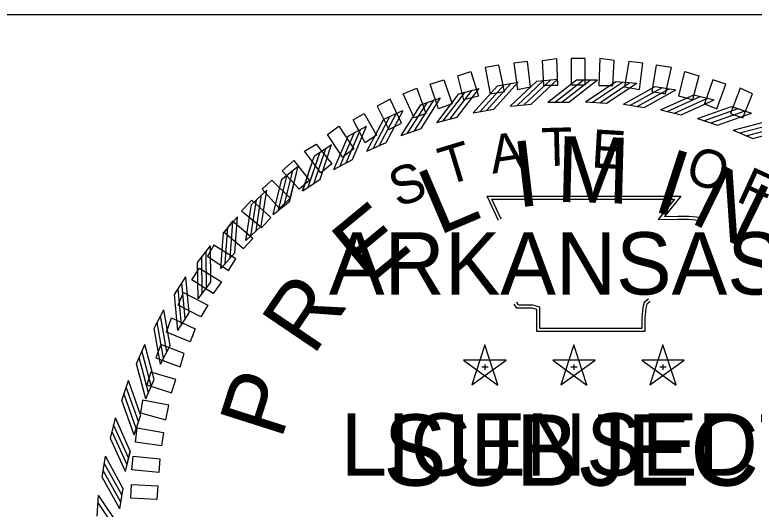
# Model space of a CAD drawing. Extents: x 16 to 1228740, y 11 to 152440.
# Drawn here: x 17.6649 to 17.7977, y 10.9098 to 10.9986 of the extents above; entities that cross this region are included whole.
import ezdxf

# ---------------------------------------------------------------- set-up
doc = ezdxf.new("R2010")
doc.units = 0
for name, color, linetype in [('R_No Plot', 7, 'Continuous'), ('STAMP_FRED', 7, 'Continuous'), ('STAMP_JUSTIN', 7, 'Continuous'), ('STAMP_PRELIM', 7, 'Continuous')]:
    doc.layers.add(name, color=color, linetype=linetype)

msp = doc.modelspace()

# ---------------------------------------------------------------- linework, layer by layer
at = {"layer": 'R_No Plot'}
msp.add_line((17.888, 10.99864), (17.47349, 10.99864), dxfattribs=at)
at = {"layer": 'STAMP_FRED'}
for p, q in [((17.75163, 10.98587), (17.75535, 10.98652)), ((17.75869, 10.98671), (17.76244, 10.98706)), ((17.76583, 10.98692), (17.7696, 10.98692)), ((17.77289, 10.98664), (17.77665, 10.98636)), ((17.74467, 10.98445), (17.74832, 10.9854)), ((17.77994, 10.98572), (17.78366, 10.98514)), ((17.78688, 10.98423), (17.79055, 10.98334)), ((17.73785, 10.98245), (17.7414, 10.98371)), ((17.75393, 10.98224), (17.7577, 10.98259)), ((17.76068, 10.98291), (17.76446, 10.98291)), ((17.76746, 10.98302), (17.77123, 10.98274)), ((17.77423, 10.98256), (17.77796, 10.98197)), ((17.73122, 10.9799), (17.73465, 10.98145)), ((17.74726, 10.98102), (17.75098, 10.98168)), ((17.78094, 10.98155), (17.78461, 10.98066)), ((17.79369, 10.98217), (17.79726, 10.98098)), ((17.74072, 10.97926), (17.74437, 10.98022)), ((17.78754, 10.97999), (17.79112, 10.97879)), ((17.72482, 10.97681), (17.72811, 10.97864)), ((17.73434, 10.97696), (17.7379, 10.97821)), ((17.79398, 10.97789), (17.79746, 10.9764)), ((17.71869, 10.97321), (17.72183, 10.9753)), ((17.72817, 10.97413), (17.73161, 10.97568)), ((17.72225, 10.97081), (17.72556, 10.97264)), ((17.71289, 10.96911), (17.71584, 10.97145)), ((17.71664, 10.96702), (17.71978, 10.96911)), ((17.70744, 10.96454), (17.71019, 10.96712)), ((17.71135, 10.96277), (17.71431, 10.96512)), ((17.70239, 10.95954), (17.70492, 10.96234)), ((17.70643, 10.9581), (17.70919, 10.96068)), ((17.69777, 10.95414), (17.70006, 10.95714)), ((17.70192, 10.95304), (17.70445, 10.95584)), ((17.69361, 10.94838), (17.69564, 10.95156)), ((17.69784, 10.94762), (17.70013, 10.95062)), ((17.68994, 10.9423), (17.69171, 10.94563)), ((17.69422, 10.94189), (17.69625, 10.94507)), ((17.68679, 10.93593), (17.68827, 10.93939)), ((17.69108, 10.93587), (17.69285, 10.93921)), ((17.74935, 10.93936), (17.747, 10.93212)), ((17.7517, 10.93212), (17.74936, 10.93936)), ((17.76534, 10.93936), (17.76299, 10.93212)), ((17.76769, 10.93212), (17.76535, 10.93936)), ((17.78134, 10.93936), (17.77898, 10.93212)), ((17.78369, 10.93212), (17.78134, 10.93936)), ((17.75316, 10.93659), (17.74555, 10.9366)), ((17.74555, 10.93659), (17.7517, 10.93211)), ((17.747, 10.93212), (17.75317, 10.93659)), ((17.76915, 10.93659), (17.76154, 10.9366)), ((17.76154, 10.93659), (17.7677, 10.93211)), ((17.763, 10.93212), (17.76916, 10.93659)), ((17.78514, 10.93659), (17.77753, 10.9366)), ((17.77753, 10.93659), (17.78369, 10.93211)), ((17.77899, 10.93212), (17.78515, 10.93659)), ((17.74881, 10.93538), (17.74994, 10.93538)), ((17.74936, 10.93578), (17.74936, 10.93483)), ((17.7648, 10.93538), (17.76593, 10.93538)), ((17.76535, 10.93578), (17.76535, 10.93483)), ((17.78079, 10.93538), (17.78193, 10.93538)), ((17.78134, 10.93578), (17.78134, 10.93483)), ((17.68417, 10.92932), (17.68536, 10.9329)), ((17.68845, 10.92962), (17.68994, 10.93309)), ((17.68635, 10.92317), (17.68755, 10.92676)), ((17.68211, 10.92252), (17.683, 10.92618)), ((17.68479, 10.91657), (17.68568, 10.92024)), ((17.68061, 10.91557), (17.6812, 10.9193)), ((17.68378, 10.90987), (17.68437, 10.9136)), ((17.6797, 10.90852), (17.67998, 10.91228))]:
    msp.add_line(p, q, dxfattribs=at)
for points in [[(17.75098, 10.98168), (17.75535, 10.98653)], [(17.75393, 10.98224), (17.75868, 10.98671)], [(17.75514, 10.98234), (17.75989, 10.98681)], [(17.75644, 10.98249), (17.76119, 10.98696)], [(17.75769, 10.98259), (17.76245, 10.98706)], [(17.76068, 10.98291), (17.76582, 10.98692)], [(17.76189, 10.9829), (17.76704, 10.98691)], [(17.7632, 10.98292), (17.76835, 10.98694)], [(17.76446, 10.98291), (17.7696, 10.98692)], [(17.76746, 10.98301), (17.77288, 10.98664)], [(17.76867, 10.98291), (17.77409, 10.98654)], [(17.76998, 10.98284), (17.7754, 10.98647)], [(17.74436, 10.98022), (17.74832, 10.98541)], [(17.74726, 10.98102), (17.75163, 10.98586)], [(17.74846, 10.98122), (17.75282, 10.98606)], [(17.74974, 10.98148), (17.75411, 10.98632)], [(17.77123, 10.98274), (17.77665, 10.98636)], [(17.77423, 10.98256), (17.77993, 10.98572)], [(17.77542, 10.98236), (17.78113, 10.98552)], [(17.77672, 10.98218), (17.78243, 10.98535)], [(17.74071, 10.97925), (17.74467, 10.98444)], [(17.74189, 10.97955), (17.74584, 10.98474)], [(17.74315, 10.97991), (17.7471, 10.9851)], [(17.77796, 10.98198), (17.78366, 10.98514)], [(17.78093, 10.98155), (17.78688, 10.98423)], [(17.78211, 10.98125), (17.78805, 10.98393)], [(17.73548, 10.97734), (17.73899, 10.98284)], [(17.73671, 10.97781), (17.74022, 10.98331)], [(17.73789, 10.97822), (17.74141, 10.98371)], [(17.78339, 10.98097), (17.78933, 10.98365)], [(17.7846, 10.98066), (17.79055, 10.98334)], [(17.73161, 10.97568), (17.73466, 10.98145)], [(17.73433, 10.97695), (17.73784, 10.98245)], [(17.78753, 10.97999), (17.79368, 10.98217)], [(17.78868, 10.97959), (17.79483, 10.98177)], [(17.78993, 10.9792), (17.79608, 10.98139)], [(17.72817, 10.97413), (17.73121, 10.9799)], [(17.72928, 10.97462), (17.73232, 10.98038)], [(17.73046, 10.97518), (17.73351, 10.98095)], [(17.79112, 10.9788), (17.79727, 10.98098)], [(17.72556, 10.97264), (17.72812, 10.97864)], [(17.79398, 10.97788), (17.80029, 10.97955)], [(17.79509, 10.9774), (17.8014, 10.97906)], [(17.79631, 10.97691), (17.80261, 10.97857)], [(17.72332, 10.97139), (17.72588, 10.97739)], [(17.72445, 10.97205), (17.72701, 10.97805)], [(17.79746, 10.9764), (17.80376, 10.97807)], [(17.72225, 10.97081), (17.72481, 10.97681)], [(17.71872, 10.96843), (17.72078, 10.97462)], [(17.71977, 10.96911), (17.72183, 10.9753)], [(17.71663, 10.96701), (17.71869, 10.9732)], [(17.71765, 10.96767), (17.7197, 10.97387)], [(17.71331, 10.96434), (17.71485, 10.97068)], [(17.7143, 10.96512), (17.71584, 10.97146)], [(17.71231, 10.96351), (17.71384, 10.96985)], [(17.71135, 10.96276), (17.71289, 10.9691)], [(17.70918, 10.96068), (17.71019, 10.96713)], [(17.70732, 10.95891), (17.70833, 10.96536)], [(17.70826, 10.95983), (17.70927, 10.96628)], [(17.75178, 10.96169), (17.74977, 10.96604), (17.78454, 10.96606), (17.78164, 10.96241), (17.784, 10.96244), (17.78597, 10.96247), (17.78794, 10.96225)], [(17.75228, 10.96192), (17.75063, 10.96549), (17.7834, 10.96551), (17.78048, 10.96185), (17.78401, 10.96189), (17.78595, 10.96192), (17.78788, 10.96171)], [(17.70643, 10.95809), (17.70744, 10.96454)], [(17.7036, 10.95491), (17.70407, 10.96142)], [(17.70445, 10.95584), (17.70492, 10.96234)], [(17.70274, 10.95392), (17.70321, 10.96043)], [(17.70192, 10.95303), (17.70239, 10.95954)], [(17.69935, 10.94963), (17.69929, 10.95615)], [(17.70012, 10.95062), (17.70006, 10.95714)], [(17.69858, 10.94857), (17.69851, 10.9551)], [(17.69784, 10.94761), (17.69777, 10.95414)], [(17.69625, 10.94507), (17.69564, 10.95156)], [(17.69488, 10.9429), (17.69427, 10.94939)], [(17.69556, 10.94401), (17.69496, 10.95051)], [(17.69422, 10.94188), (17.69361, 10.94838)], [(17.77906, 10.94712), (17.77847, 10.94664), (17.77827, 10.94592), (17.77808, 10.94411), (17.77808, 10.94171), (17.75867, 10.94171), (17.75867, 10.94495), (17.75867, 10.94567), (17.75788, 10.94592), (17.75512, 10.94592), (17.75463, 10.94666)], [(17.77872, 10.94755), (17.77799, 10.94695), (17.77773, 10.94602), (17.77753, 10.94414), (17.77753, 10.94226), (17.75922, 10.94226), (17.75922, 10.94495), (17.75922, 10.94608), (17.75796, 10.94647), (17.75542, 10.94647), (17.75509, 10.94697)], [(17.69284, 10.93921), (17.6917, 10.94563)], [(17.69225, 10.9381), (17.69111, 10.94453)], [(17.69166, 10.93693), (17.69052, 10.94336)], [(17.69108, 10.93587), (17.68994, 10.94229)], [(17.68994, 10.93309), (17.68827, 10.9394)], [(17.68943, 10.93194), (17.68777, 10.93825)], [(17.68894, 10.93072), (17.68728, 10.93703)], [(17.68846, 10.92961), (17.68679, 10.93592)], [(17.68754, 10.92675), (17.68536, 10.9329)], [(17.68713, 10.92557), (17.68495, 10.93171)], [(17.68675, 10.92431), (17.68457, 10.93046)], [(17.68635, 10.92317), (17.68417, 10.92931)], [(17.68568, 10.92024), (17.683, 10.92619)], [(17.68537, 10.91902), (17.68269, 10.92497)], [(17.68509, 10.91774), (17.68241, 10.92369)], [(17.68479, 10.91657), (17.68211, 10.92251)], [(17.68436, 10.91359), (17.6812, 10.9193)], [(17.68416, 10.91236), (17.68099, 10.91806)], [(17.68398, 10.91106), (17.68082, 10.91676)], [(17.68378, 10.90986), (17.68062, 10.91557)], [(17.6836, 10.90686), (17.67997, 10.91229)], [(17.68349, 10.90561), (17.67987, 10.91104)]]:
    msp.add_lwpolyline(points, dxfattribs=at)
at = {"layer": 'STAMP_JUSTIN'}
for p, q in [((17.75163, 10.98587), (17.75535, 10.98652)), ((17.75869, 10.98671), (17.76244, 10.98706)), ((17.76583, 10.98692), (17.7696, 10.98692)), ((17.77289, 10.98664), (17.77665, 10.98636)), ((17.74467, 10.98444), (17.74832, 10.9854)), ((17.77994, 10.98572), (17.78366, 10.98514)), ((17.78688, 10.98423), (17.79055, 10.98334)), ((17.73785, 10.98245), (17.7414, 10.98371)), ((17.75393, 10.98224), (17.7577, 10.98259)), ((17.76068, 10.98291), (17.76446, 10.98291)), ((17.76746, 10.98301), (17.77123, 10.98274)), ((17.77423, 10.98256), (17.77796, 10.98197)), ((17.73122, 10.9799), (17.73465, 10.98145)), ((17.74726, 10.98102), (17.75098, 10.98168)), ((17.78094, 10.98155), (17.78461, 10.98065)), ((17.79368, 10.98217), (17.79726, 10.98098)), ((17.74072, 10.97926), (17.74437, 10.98022)), ((17.78754, 10.97999), (17.79112, 10.97879)), ((17.72482, 10.97681), (17.72811, 10.97864)), ((17.73434, 10.97695), (17.7379, 10.97821)), ((17.79398, 10.97788), (17.79746, 10.9764)), ((17.71869, 10.97321), (17.72183, 10.9753)), ((17.72817, 10.97413), (17.73162, 10.97568)), ((17.72226, 10.97081), (17.72556, 10.97264)), ((17.71289, 10.96911), (17.71584, 10.97145)), ((17.71664, 10.96702), (17.71978, 10.96911)), ((17.70744, 10.96454), (17.71019, 10.96712)), ((17.71135, 10.96277), (17.71431, 10.96512)), ((17.70239, 10.95954), (17.70492, 10.96234)), ((17.70643, 10.9581), (17.70919, 10.96068)), ((17.69777, 10.95414), (17.70006, 10.95714)), ((17.70192, 10.95304), (17.70445, 10.95584)), ((17.69361, 10.94838), (17.69565, 10.95156)), ((17.69784, 10.94762), (17.70013, 10.95062)), ((17.68994, 10.9423), (17.69171, 10.94563)), ((17.69422, 10.94189), (17.69625, 10.94507)), ((17.68679, 10.93593), (17.68827, 10.93939)), ((17.69108, 10.93587), (17.69285, 10.93921)), ((17.74935, 10.93936), (17.747, 10.93212)), ((17.7517, 10.93212), (17.74936, 10.93936)), ((17.76534, 10.93936), (17.76299, 10.93212)), ((17.76769, 10.93212), (17.76535, 10.93936)), ((17.78134, 10.93936), (17.77898, 10.93212)), ((17.78369, 10.93212), (17.78134, 10.93936)), ((17.75316, 10.93659), (17.74555, 10.9366)), ((17.74555, 10.93659), (17.7517, 10.93211)), ((17.747, 10.93212), (17.75317, 10.93659)), ((17.76915, 10.93659), (17.76154, 10.9366)), ((17.76154, 10.93659), (17.7677, 10.93211)), ((17.76299, 10.93212), (17.76916, 10.93659)), ((17.78514, 10.93659), (17.77753, 10.9366)), ((17.77753, 10.93659), (17.78369, 10.93211)), ((17.77899, 10.93212), (17.78515, 10.93659)), ((17.74881, 10.93538), (17.74994, 10.93538)), ((17.74936, 10.93578), (17.74936, 10.93483)), ((17.7648, 10.93538), (17.76593, 10.93538)), ((17.76535, 10.93578), (17.76535, 10.93483)), ((17.78079, 10.93538), (17.78193, 10.93538)), ((17.78134, 10.93578), (17.78134, 10.93483)), ((17.68417, 10.92932), (17.68536, 10.9329)), ((17.68846, 10.92962), (17.68994, 10.93309)), ((17.68635, 10.92317), (17.68755, 10.92676)), ((17.68211, 10.92252), (17.683, 10.92618)), ((17.68479, 10.91657), (17.68569, 10.92024)), ((17.68062, 10.91557), (17.6812, 10.9193)), ((17.68378, 10.90987), (17.68437, 10.9136)), ((17.6797, 10.90853), (17.67998, 10.91228))]:
    msp.add_line(p, q, dxfattribs=at)
for points in [[(17.75098, 10.98168), (17.75535, 10.98653)], [(17.75393, 10.98224), (17.75868, 10.98671)], [(17.75514, 10.98234), (17.75989, 10.98681)], [(17.75644, 10.98249), (17.76119, 10.98696)], [(17.75769, 10.98259), (17.76245, 10.98706)], [(17.76068, 10.98291), (17.76582, 10.98692)], [(17.76189, 10.98289), (17.76704, 10.98691)], [(17.7632, 10.98292), (17.76835, 10.98693)], [(17.76446, 10.98291), (17.7696, 10.98692)], [(17.76746, 10.98301), (17.77288, 10.98663)], [(17.76867, 10.98291), (17.77409, 10.98653)], [(17.74437, 10.98022), (17.74832, 10.98541)], [(17.74726, 10.98102), (17.75163, 10.98586)], [(17.74846, 10.98122), (17.75282, 10.98606)], [(17.74974, 10.98147), (17.75411, 10.98632)], [(17.76998, 10.98284), (17.7754, 10.98647)], [(17.77123, 10.98274), (17.77665, 10.98636)], [(17.77423, 10.98256), (17.77993, 10.98572)], [(17.77542, 10.98236), (17.78113, 10.98552)], [(17.77672, 10.98218), (17.78243, 10.98535)], [(17.74071, 10.97925), (17.74467, 10.98444)], [(17.74189, 10.97955), (17.74584, 10.98474)], [(17.74315, 10.97991), (17.7471, 10.9851)], [(17.77796, 10.98198), (17.78366, 10.98514)], [(17.78093, 10.98155), (17.78688, 10.98423)], [(17.78211, 10.98125), (17.78805, 10.98393)], [(17.73548, 10.97734), (17.73899, 10.98284)], [(17.73671, 10.97781), (17.74022, 10.9833)], [(17.73789, 10.97822), (17.74141, 10.98371)], [(17.78339, 10.98097), (17.78933, 10.98365)], [(17.7846, 10.98066), (17.79055, 10.98334)], [(17.73161, 10.97568), (17.73466, 10.98145)], [(17.73433, 10.97695), (17.73785, 10.98245)], [(17.78753, 10.97998), (17.79368, 10.98216)], [(17.78868, 10.97959), (17.79483, 10.98177)], [(17.78993, 10.9792), (17.79608, 10.98138)], [(17.72817, 10.97413), (17.73121, 10.9799)], [(17.72928, 10.97462), (17.73232, 10.98038)], [(17.73046, 10.97518), (17.73351, 10.98095)], [(17.79112, 10.9788), (17.79727, 10.98098)], [(17.72556, 10.97264), (17.72812, 10.97864)], [(17.79398, 10.97788), (17.80029, 10.97955)], [(17.79509, 10.9774), (17.8014, 10.97906)], [(17.7963, 10.97691), (17.80261, 10.97857)], [(17.72332, 10.97139), (17.72588, 10.97739)], [(17.72445, 10.97204), (17.72701, 10.97804)], [(17.79746, 10.9764), (17.80376, 10.97807)], [(17.72225, 10.97081), (17.72481, 10.97681)], [(17.71872, 10.96842), (17.72078, 10.97462)], [(17.71978, 10.96911), (17.72183, 10.9753)], [(17.71664, 10.96701), (17.71869, 10.9732)], [(17.71765, 10.96767), (17.71971, 10.97386)], [(17.71331, 10.96434), (17.71485, 10.97068)], [(17.71431, 10.96512), (17.71584, 10.97145)], [(17.71231, 10.96351), (17.71384, 10.96985)], [(17.71135, 10.96276), (17.71289, 10.9691)], [(17.70918, 10.96068), (17.71019, 10.96713)], [(17.70733, 10.95891), (17.70833, 10.96536)], [(17.70826, 10.95983), (17.70927, 10.96627)], [(17.75178, 10.96169), (17.74977, 10.96604), (17.78454, 10.96606), (17.78164, 10.96241), (17.784, 10.96244), (17.78597, 10.96247), (17.78794, 10.96225)], [(17.75228, 10.96192), (17.75063, 10.96549), (17.7834, 10.96551), (17.78048, 10.96185), (17.78401, 10.96189), (17.78595, 10.96192), (17.78788, 10.96171)], [(17.70643, 10.95809), (17.70744, 10.96454)], [(17.7036, 10.95491), (17.70407, 10.96142)], [(17.70445, 10.95584), (17.70492, 10.96234)], [(17.70274, 10.95392), (17.70321, 10.96043)], [(17.70192, 10.95303), (17.70239, 10.95954)], [(17.69935, 10.94963), (17.69929, 10.95615)], [(17.70013, 10.95062), (17.70006, 10.95714)], [(17.69858, 10.94857), (17.69852, 10.95509)], [(17.69784, 10.94761), (17.69777, 10.95414)], [(17.69625, 10.94507), (17.69564, 10.95156)], [(17.69488, 10.9429), (17.69428, 10.94939)], [(17.69556, 10.94401), (17.69496, 10.95051)], [(17.69422, 10.94188), (17.69361, 10.94838)], [(17.77906, 10.94712), (17.77847, 10.94664), (17.77827, 10.94592), (17.77808, 10.94411), (17.77808, 10.94171), (17.75867, 10.94171), (17.75867, 10.94495), (17.75867, 10.94567), (17.75788, 10.94592), (17.75512, 10.94592), (17.75463, 10.94666)], [(17.77871, 10.94755), (17.77799, 10.94695), (17.77773, 10.94602), (17.77753, 10.94414), (17.77753, 10.94226), (17.75922, 10.94226), (17.75922, 10.94495), (17.75922, 10.94608), (17.75796, 10.94647), (17.75542, 10.94647), (17.75509, 10.94697)], [(17.69285, 10.93921), (17.69171, 10.94563)], [(17.69225, 10.9381), (17.69111, 10.94453)], [(17.69166, 10.93693), (17.69052, 10.94336)], [(17.69108, 10.93587), (17.68994, 10.94229)], [(17.68994, 10.93309), (17.68827, 10.9394)], [(17.68943, 10.93194), (17.68777, 10.93825)], [(17.68894, 10.93073), (17.68728, 10.93703)], [(17.68846, 10.92961), (17.68679, 10.93592)], [(17.68754, 10.92675), (17.68536, 10.9329)], [(17.68714, 10.92557), (17.68495, 10.93171)], [(17.68675, 10.92431), (17.68457, 10.93046)], [(17.68636, 10.92317), (17.68417, 10.92931)], [(17.68568, 10.92024), (17.683, 10.92619)], [(17.68537, 10.91902), (17.68269, 10.92497)], [(17.68509, 10.91774), (17.68241, 10.92369)], [(17.68479, 10.91657), (17.68211, 10.92251)], [(17.68436, 10.9136), (17.6812, 10.9193)], [(17.68416, 10.91236), (17.68099, 10.91806)], [(17.68398, 10.91106), (17.68082, 10.91676)], [(17.68378, 10.90986), (17.68062, 10.91557)], [(17.6836, 10.90686), (17.67998, 10.91229)], [(17.6835, 10.90561), (17.67987, 10.91104)]]:
    msp.add_lwpolyline(points, dxfattribs=at)
at = {"layer": 'STAMP_PRELIM'}
for p, q in [((17.75971, 10.99041), (17.76221, 10.99078)), ((17.76221, 10.99078), (17.7624, 10.98591)), ((17.7674, 10.99078), (17.76484, 10.99078)), ((17.76484, 10.99078), (17.76484, 10.98603)), ((17.7674, 10.98603), (17.7674, 10.99078)), ((17.77003, 10.99078), (17.76984, 10.98591)), ((17.77259, 10.99041), (17.77003, 10.99078)), ((17.75184, 10.9896), (17.7494, 10.98916)), ((17.7494, 10.98916), (17.75034, 10.98441)), ((17.7529, 10.98485), (17.75184, 10.9896)), ((17.75703, 10.99022), (17.75459, 10.98997)), ((17.75459, 10.98997), (17.75521, 10.98522)), ((17.75753, 10.98566), (17.75703, 10.99022)), ((17.75996, 10.98591), (17.75971, 10.99041)), ((17.77234, 10.98591), (17.77259, 10.99041)), ((17.77521, 10.99022), (17.77446, 10.98566)), ((17.77771, 10.98997), (17.77521, 10.99022)), ((17.77715, 10.98522), (17.77771, 10.98997)), ((17.78015, 10.9896), (17.77934, 10.98485)), ((17.7829, 10.98916), (17.78015, 10.9896)), ((17.78178, 10.98441), (17.7829, 10.98916)), ((17.74453, 10.98766), (17.74684, 10.98847)), ((17.74684, 10.98847), (17.74821, 10.98403)), ((17.78421, 10.98403), (17.78528, 10.98847)), ((17.78528, 10.98847), (17.78778, 10.98766)), ((17.73953, 10.98616), (17.74196, 10.98697)), ((17.74196, 10.98697), (17.74346, 10.98266)), ((17.74559, 10.98335), (17.74453, 10.98766)), ((17.78778, 10.98766), (17.78665, 10.98335)), ((17.79033, 10.98697), (17.78883, 10.98266)), ((17.79265, 10.98616), (17.79033, 10.98697)), ((17.73471, 10.98441), (17.73715, 10.98547)), ((17.73715, 10.98547), (17.73878, 10.98091)), ((17.74103, 10.98172), (17.73953, 10.98616)), ((17.75521, 10.98522), (17.75753, 10.98566)), ((17.7624, 10.98591), (17.75996, 10.98591)), ((17.76484, 10.98603), (17.7674, 10.98603)), ((17.76984, 10.98591), (17.77234, 10.98591)), ((17.77446, 10.98566), (17.77715, 10.98522)), ((17.79103, 10.98172), (17.79265, 10.98616)), ((17.79521, 10.98547), (17.79346, 10.98091)), ((17.7974, 10.98441), (17.79521, 10.98547)), ((17.73665, 10.9801), (17.73471, 10.98441)), ((17.74821, 10.98403), (17.74559, 10.98335)), ((17.75034, 10.98441), (17.7529, 10.98485)), ((17.77934, 10.98485), (17.78178, 10.98441)), ((17.78665, 10.98335), (17.78421, 10.98403)), ((17.79571, 10.9801), (17.7974, 10.98441)), ((17.73234, 10.98347), (17.73003, 10.98222)), ((17.7344, 10.97916), (17.73234, 10.98347)), ((17.74346, 10.98266), (17.74103, 10.98172)), ((17.78883, 10.98266), (17.79103, 10.98172)), ((17.73003, 10.98222), (17.73209, 10.97803)), ((17.72571, 10.97978), (17.72771, 10.98091)), ((17.72771, 10.98091), (17.7299, 10.97703)), ((17.73878, 10.98091), (17.73665, 10.9801)), ((17.79346, 10.98091), (17.79571, 10.9801)), ((17.72109, 10.9771), (17.72315, 10.9786)), ((17.72315, 10.9786), (17.72584, 10.97453)), ((17.72784, 10.9756), (17.72571, 10.97978)), ((17.73209, 10.97803), (17.7344, 10.97916)), ((17.72378, 10.97303), (17.72109, 10.9771)), ((17.7299, 10.97703), (17.72784, 10.9756)), ((17.71696, 10.9741), (17.71909, 10.97541)), ((17.71909, 10.97541), (17.7219, 10.97185)), ((17.72584, 10.97453), (17.72378, 10.97303)), ((17.7199, 10.97022), (17.71696, 10.9741)), ((17.71296, 10.9706), (17.71503, 10.97247)), ((17.71503, 10.97247), (17.71784, 10.96885)), ((17.71603, 10.96728), (17.71296, 10.9706)), ((17.7219, 10.97185), (17.7199, 10.97022)), ((17.70934, 10.96728), (17.71109, 10.96891)), ((17.71109, 10.96891), (17.7144, 10.96566)), ((17.71784, 10.96885), (17.71603, 10.96728)), ((17.71246, 10.96385), (17.70934, 10.96728)), ((17.70753, 10.96535), (17.70565, 10.96341)), ((17.7109, 10.96222), (17.70753, 10.96535)), ((17.7144, 10.96566), (17.71246, 10.96385)), ((17.70565, 10.96341), (17.70928, 10.96041)), ((17.70403, 10.96153), (17.70253, 10.9596)), ((17.70771, 10.95841), (17.70403, 10.96153)), ((17.70928, 10.96041), (17.7109, 10.96222)), ((17.70253, 10.9596), (17.70603, 10.95666)), ((17.70603, 10.95666), (17.70771, 10.95841)), ((17.70071, 10.95722), (17.69953, 10.95528)), ((17.70465, 10.95478), (17.70071, 10.95722)), ((17.69953, 10.95528), (17.70334, 10.95266)), ((17.70334, 10.95266), (17.70465, 10.95478)), ((17.69671, 10.95103), (17.69809, 10.9531)), ((17.69809, 10.9531), (17.70203, 10.95066)), ((17.70059, 10.94853), (17.69671, 10.95103)), ((17.70203, 10.95066), (17.70059, 10.94853)), ((17.69428, 10.94647), (17.69521, 10.94872)), ((17.69521, 10.94872), (17.69959, 10.94647)), ((17.69834, 10.94435), (17.69428, 10.94647)), ((17.69959, 10.94647), (17.69834, 10.94435)), ((17.69221, 10.9416), (17.69309, 10.94416)), ((17.69309, 10.94416), (17.69734, 10.94222)), ((17.69646, 10.93985), (17.69221, 10.9416)), ((17.69734, 10.94222), (17.69646, 10.93985)), ((17.69115, 10.93941), (17.69028, 10.93697)), ((17.69534, 10.93778), (17.69115, 10.93941)), ((17.69465, 10.93535), (17.69534, 10.93778)), ((17.69028, 10.93697), (17.69465, 10.93535)), ((17.68934, 10.93441), (17.68865, 10.93216)), ((17.69384, 10.9331), (17.68934, 10.93441)), ((17.68865, 10.93216), (17.69309, 10.93072)), ((17.69309, 10.93072), (17.69384, 10.9331)), ((17.6879, 10.92941), (17.68753, 10.9271)), ((17.69259, 10.92847), (17.6879, 10.92941)), ((17.69209, 10.92585), (17.69259, 10.92847)), ((17.68753, 10.9271), (17.69209, 10.92585)), ((17.68659, 10.92185), (17.6869, 10.92441)), ((17.6869, 10.92441), (17.69165, 10.9236)), ((17.69165, 10.9236), (17.69128, 10.92116)), ((17.69128, 10.92116), (17.68659, 10.92185)), ((17.68596, 10.91685), (17.68621, 10.91935)), ((17.68621, 10.91935), (17.69096, 10.91885)), ((17.69096, 10.91885), (17.69078, 10.91641)), ((17.69078, 10.91641), (17.68596, 10.91685)), ((17.68578, 10.91178), (17.6859, 10.91422)), ((17.6859, 10.91422), (17.69065, 10.91397)), ((17.69065, 10.91397), (17.69046, 10.91153)), ((17.69046, 10.91153), (17.68578, 10.91178))]:
    msp.add_line(p, q, dxfattribs=at)

# ---------------------------------------------------------------- texts
at = {"layer": 'STAMP_FRED'}
for s, rotation, p in [('A', 8.6788, (17.75072, 10.97006)), ('T', 1.4789, (17.75958, 10.97142)), ('E', 356.672, (17.76836, 10.97122)), ('T', 16.9015, (17.74239, 10.96789)), ('O', 341.2218, (17.78501, 10.96886)), ('S', 19.7726, (17.73367, 10.96397)), ('F', 335.3628, (17.79425, 10.96525))]:
    msp.add_text(s, height=0.00686, rotation=rotation, dxfattribs=at).set_placement(p)
for s, p in [('ARKANSAS', (17.72135, 10.94837)), ('LICENSED', (17.72348, 10.91583))]:
    msp.add_text(s, height=0.011194, dxfattribs=at).set_placement(p)
at = {"layer": 'STAMP_JUSTIN'}
for s, rotation, p in [('A', 8.6788, (17.75072, 10.97006)), ('T', 1.4789, (17.75958, 10.97142)), ('E', 356.672, (17.76836, 10.97122)), ('T', 16.9015, (17.74239, 10.96789)), ('O', 341.2218, (17.78501, 10.96886)), ('S', 19.7726, (17.73367, 10.96397)), ('F', 335.3628, (17.79425, 10.96525))]:
    msp.add_text(s, height=0.00686, rotation=rotation, dxfattribs=at).set_placement(p)
for s, p in [('ARKANSAS', (17.72135, 10.94837)), ('LICENSED', (17.72348, 10.91583))]:
    msp.add_text(s, height=0.011194, dxfattribs=at).set_placement(p)
at = {"layer": 'STAMP_PRELIM'}
for s, rotation, p in [('I', 6.6752, (17.75515, 10.96397)), ('M', 358.4667, (17.76209, 10.96503)), ('I', 342.0495, (17.77921, 10.96353)), ('L', 23.0924, (17.74103, 10.95891)), ('N', 333.841, (17.7859, 10.96147)), ('E', 39.5095, (17.7284, 10.94985)), ('R', 55.9266, (17.71853, 10.93716)), ('P', 72.3438, (17.71278, 10.9221))]:
    msp.add_text(s, height=0.01184, rotation=rotation, dxfattribs=at).set_placement(p)
msp.add_text('SUBJECT', height=0.012794, dxfattribs=at).set_placement((17.73109, 10.91403))

doc.saveas('drawing.dxf')
